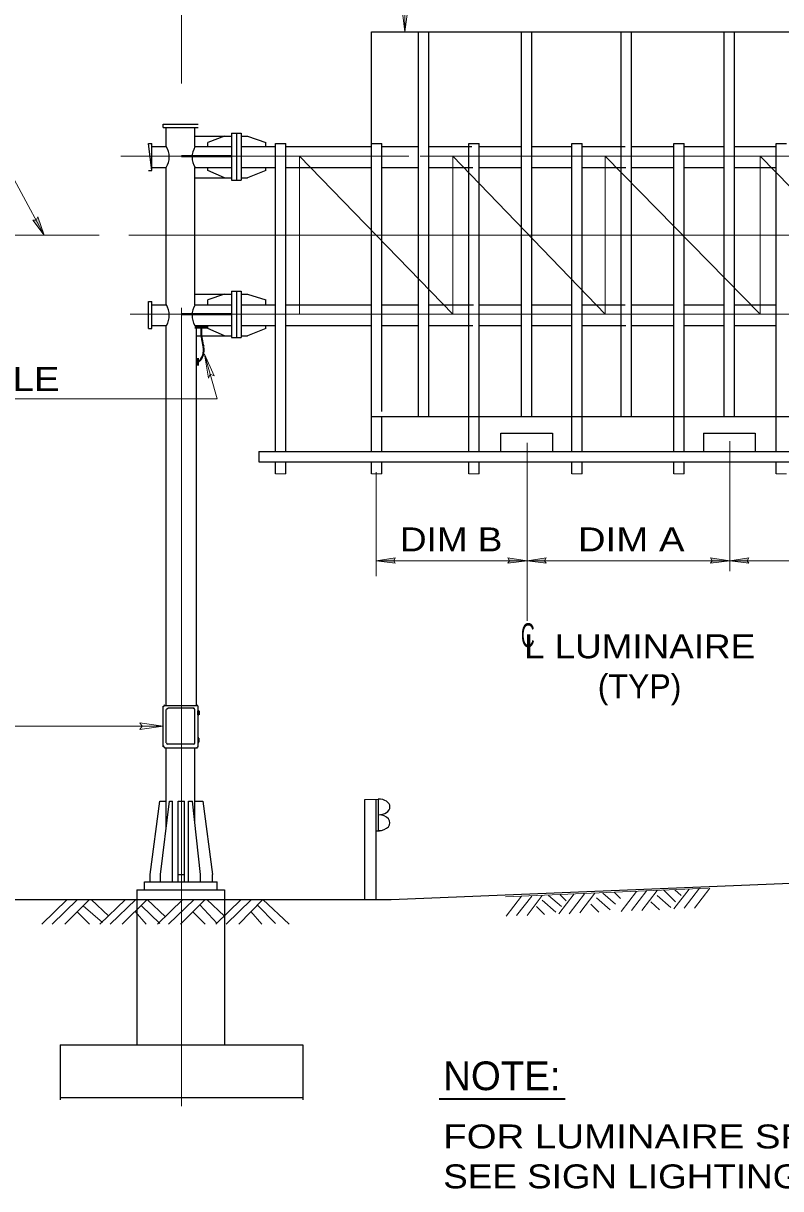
# Model space of a CAD drawing. Extents: x 312601.858 to 312602.699, y 144420.109 to 144420.704.
# Drawn here: x 312601.9635 to 312602.0584, y 144420.4634 to 144420.6093 of the extents above; entities that cross this region are included whole.
import ezdxf
from ezdxf.enums import TextEntityAlignment as Align

# ---------------------------------------------------------------- set-up
doc = ezdxf.new("R2010")
doc.units = 0
doc.header["$LTSCALE"] = 0.0012
for name, pattern in [('DOT_DASHED', [7.7, 5, -1.2, 0.3, -1.2]), ('LONG_DASH_SHORT_DASH', [9.9, 6, -1.2, 1.5, -1.2]), ('LONG_DASHED', [7.5, 6, -1.5])]:
    doc.linetypes.add(name, pattern=pattern)
for name, color, linetype, lineweight in [('1', 7, 'Continuous', 25), ('2', 7, 'Continuous', 25), ('39', 7, 'Continuous', 13)]:
    doc.layers.add(name, color=color, linetype=linetype, lineweight=lineweight)

msp = doc.modelspace()

# ---------------------------------------------------------------- hatches: boundary and pattern name
at = {"layer": '1'}
for points in [[(312601.9854, 144420.5232), (312601.9855, 144420.5232), (312601.9855, 144420.5227), (312601.9854, 144420.5227)], [(312601.9854, 144420.5193), (312601.9855, 144420.5193), (312601.9855, 144420.5198), (312601.9854, 144420.5198)]]:
    msp.add_hatch(color=256, dxfattribs=at).paths.add_polyline_path(points)
at = {"layer": '39'}
for points in [[(312601.9651, 144420.5847), (312601.9653, 144420.5851), (312601.9661, 144420.5828), (312601.9647, 144420.5847)], [(312602.0099, 144420.542), (312602.0101, 144420.5417), (312602.0077, 144420.542), (312602.0101, 144420.5424)], [(312602.0244, 144420.542), (312602.0242, 144420.5424), (312602.0266, 144420.542), (312602.0242, 144420.5417)], [(312602.0288, 144420.542), (312602.029, 144420.5417), (312602.0266, 144420.542), (312602.029, 144420.5424)], [(312602.0498, 144420.542), (312602.0496, 144420.5424), (312602.052, 144420.542), (312602.0496, 144420.5417)], [(312602.0542, 144420.542), (312602.0544, 144420.5417), (312602.052, 144420.542), (312602.0544, 144420.5424)]]:
    msp.add_hatch(color=256, dxfattribs=at).paths.add_polyline_path(points)

# ---------------------------------------------------------------- linework, layer by layer
at = {"layer": '1', "lineweight": 13}
for p, q in [((312601.9833, 144420.6415), (312601.9833, 144420.6018)), ((312602.0113, 144420.621), (312602.0113, 144420.6083)), ((312601.9548, 144420.5828), (312601.973, 144420.5828)), ((312601.9862, 144420.5679), (312601.9878, 144420.5623)), ((312601.9243, 144420.5623), (312601.9878, 144420.5623)), ((312601.9726, 144420.5623), (312601.9878, 144420.5623)), ((312601.9951, 144420.5529), (312601.9964, 144420.5529)), ((312602.0071, 144420.5529), (312602.0084, 144420.5529)), ((312602.0077, 144420.5401), (312602.0077, 144420.5531)), ((312602.0077, 144420.5437), (312602.0077, 144420.5531)), ((312602.0193, 144420.5529), (312602.0206, 144420.5529)), ((312602.0322, 144420.5529), (312602.0335, 144420.5529)), ((312602.045, 144420.5529), (312602.0463, 144420.5529)), ((312602.0578, 144420.5529), (312602.0591, 144420.5529)), ((312601.981, 144420.5213), (312601.9593, 144420.5213)), ((312601.981, 144420.5213), (312601.9605, 144420.5213)), ((312602.008, 144420.5121), (312602.0063, 144420.5121)), ((312601.9658, 144420.4965), (312601.969, 144420.4996)), ((312601.9671, 144420.4965), (312601.9703, 144420.4996)), ((312601.9687, 144420.4965), (312601.9718, 144420.4996)), ((312601.9734, 144420.4967), (312601.971, 144420.4988)), ((312601.9742, 144420.4975), (312601.972, 144420.4996)), ((312601.9731, 144420.4965), (312601.9763, 144420.4996)), ((312601.9744, 144420.4965), (312601.9776, 144420.4996)), ((312601.9759, 144420.4965), (312601.979, 144420.4996)), ((312601.9806, 144420.4966), (312601.9783, 144420.4988)), ((312601.9813, 144420.4974), (312601.979, 144420.4996)), ((312601.9803, 144420.4965), (312601.9835, 144420.4996)), ((312601.9817, 144420.4965), (312601.9849, 144420.4996)), ((312601.9832, 144420.4965), (312601.9863, 144420.4996)), ((312601.9878, 144420.4966), (312601.9856, 144420.4989)), ((312601.9887, 144420.4975), (312601.9865, 144420.4996)), ((312601.9876, 144420.4965), (312601.9908, 144420.4996)), ((312601.9889, 144420.4965), (312601.9921, 144420.4996)), ((312601.9905, 144420.4965), (312601.9935, 144420.4996)), ((312601.9951, 144420.4966), (312601.9928, 144420.4989)), ((312601.9968, 144420.4965), (312601.9935, 144420.4996)), ((312601.9718, 144420.4965), (312601.9702, 144420.4981)), ((312601.9789, 144420.4965), (312601.9775, 144420.4981)), ((312601.9863, 144420.4965), (312601.9847, 144420.4981)), ((312601.9934, 144420.4965), (312601.992, 144420.4981))]:
    msp.add_line(p, q, dxfattribs=at)
at = {"layer": '1', "linetype": 'LONG_DASH_SHORT_DASH', "lineweight": 13}
for p, q in [((312601.9833, 144420.4737), (312601.9833, 144420.6018)), ((312601.9757, 144420.5927), (312602.0118, 144420.5927)), ((312601.9769, 144420.5729), (312602.0559, 144420.5729))]:
    msp.add_line(p, q, dxfattribs=at)
at = {"layer": '1'}
for p, q in [((312601.981, 144420.5963), (312601.981, 144420.5967)), ((312601.981, 144420.5963), (312601.9854, 144420.5963)), ((312601.9814, 144420.5939), (312601.9814, 144420.5963)), ((312601.985, 144420.5939), (312601.985, 144420.5963)), ((312601.985, 144420.5952), (312601.9896, 144420.5952)), ((312601.9887, 144420.5952), (312601.9866, 144420.5944)), ((312601.9896, 144420.5956), (312601.9908, 144420.5956)), ((312601.9908, 144420.5952), (312601.9916, 144420.5952)), ((312601.9916, 144420.5952), (312601.9939, 144420.5944)), ((312601.9792, 144420.5943), (312601.9796, 144420.5943)), ((312601.9796, 144420.5909), (312601.9796, 144420.5943)), ((312601.9796, 144420.5939), (312601.9814, 144420.5939)), ((312601.985, 144420.5939), (312601.9896, 144420.5939)), ((312601.9866, 144420.5939), (312601.9866, 144420.5944)), ((312601.9908, 144420.5939), (312601.9951, 144420.5939)), ((312601.9939, 144420.5939), (312601.9939, 144420.5944)), ((312601.9964, 144420.5939), (312602.0071, 144420.5939)), ((312601.9796, 144420.5913), (312601.9814, 144420.5913)), ((312601.9814, 144420.5741), (312601.9814, 144420.5913)), ((312601.985, 144420.5741), (312601.985, 144420.5913)), ((312601.985, 144420.5913), (312601.9896, 144420.5913)), ((312601.9866, 144420.5909), (312601.9866, 144420.5913)), ((312601.9887, 144420.59), (312601.9866, 144420.5909)), ((312601.9908, 144420.5913), (312601.9951, 144420.5913)), ((312601.9939, 144420.5909), (312601.9916, 144420.59)), ((312601.9939, 144420.5909), (312601.9939, 144420.5913)), ((312601.9964, 144420.5913), (312602.0071, 144420.5913)), ((312601.985, 144420.59), (312601.9896, 144420.59)), ((312601.9896, 144420.5897), (312601.9908, 144420.5897)), ((312601.9908, 144420.59), (312601.9916, 144420.59)), ((312601.985, 144420.5754), (312601.9896, 144420.5754)), ((312601.9887, 144420.5754), (312601.9866, 144420.5747)), ((312601.9866, 144420.5741), (312601.9866, 144420.5747)), ((312601.9896, 144420.5758), (312601.9908, 144420.5758)), ((312601.9908, 144420.5754), (312601.9916, 144420.5754)), ((312601.9916, 144420.5754), (312601.9939, 144420.5747)), ((312601.9939, 144420.5741), (312601.9939, 144420.5747)), ((312601.9792, 144420.5745), (312601.9796, 144420.5745)), ((312601.9792, 144420.5711), (312601.9792, 144420.5745)), ((312601.9796, 144420.5711), (312601.9796, 144420.5745)), ((312601.9796, 144420.5741), (312601.9814, 144420.5741)), ((312601.985, 144420.5741), (312601.9896, 144420.5741)), ((312601.9908, 144420.5741), (312601.9951, 144420.5741)), ((312601.9964, 144420.5741), (312602.0071, 144420.5741)), ((312601.9792, 144420.5711), (312601.9796, 144420.5711)), ((312601.9796, 144420.5715), (312601.9814, 144420.5715)), ((312601.9814, 144420.5239), (312601.9814, 144420.5715)), ((312601.985, 144420.5715), (312601.9896, 144420.5715)), ((312601.9852, 144420.5239), (312601.9852, 144420.5715)), ((312601.9866, 144420.5711), (312601.9866, 144420.5715)), ((312601.9887, 144420.5702), (312601.9866, 144420.5711)), ((312601.9908, 144420.5715), (312601.9951, 144420.5715)), ((312601.9939, 144420.5711), (312601.9916, 144420.5702)), ((312601.9939, 144420.5711), (312601.9939, 144420.5715)), ((312601.9964, 144420.5715), (312602.0071, 144420.5715)), ((312601.9852, 144420.5702), (312601.9896, 144420.5702)), ((312601.9896, 144420.57), (312601.9908, 144420.57)), ((312601.9908, 144420.5702), (312601.9916, 144420.5702)), ((312602.0071, 144420.5601), (312602.0971, 144420.5601)), ((312601.993, 144420.5557), (312602.0971, 144420.5557)), ((312601.993, 144420.5544), (312602.0971, 144420.5544)), ((312601.981, 144420.5187), (312601.981, 144420.5238)), ((312601.9812, 144420.5239), (312601.9853, 144420.5239)), ((312601.9816, 144420.5236), (312601.9849, 144420.5236)), ((312601.9854, 144420.5187), (312601.9854, 144420.5238)), ((312601.9814, 144420.5192), (312601.9814, 144420.5234)), ((312601.985, 144420.5192), (312601.985, 144420.5234)), ((312601.9812, 144420.5186), (312601.9853, 144420.5186)), ((312601.9814, 144420.5086), (312601.9814, 144420.5186)), ((312601.9816, 144420.5191), (312601.9849, 144420.5191)), ((312601.985, 144420.5094), (312601.985, 144420.5186)), ((312601.9794, 144420.5027), (312601.9806, 144420.5119)), ((312601.9806, 144420.5119), (312601.9814, 144420.5119)), ((312601.9818, 144420.5119), (312601.9822, 144420.5119)), ((312601.9822, 144420.5018), (312601.9822, 144420.5119)), ((312601.9829, 144420.5119), (312601.9837, 144420.5119)), ((312601.9829, 144420.5018), (312601.9829, 144420.5119)), ((312601.9837, 144420.5018), (312601.9837, 144420.5119)), ((312601.985, 144420.5119), (312601.986, 144420.5119)), ((312601.986, 144420.5119), (312601.9872, 144420.5027)), ((312602.0077, 144420.5082), (312602.0081, 144420.5082)), ((312601.9787, 144420.5018), (312601.9878, 144420.5018)), ((312601.9787, 144420.5008), (312601.9787, 144420.5018)), ((312601.9794, 144420.5018), (312601.9794, 144420.5027)), ((312601.9807, 144420.5018), (312601.9807, 144420.5027)), ((312601.9829, 144420.5027), (312601.9837, 144420.5027)), ((312601.9857, 144420.5018), (312601.9857, 144420.5027)), ((312601.9872, 144420.5018), (312601.9872, 144420.5027)), ((312601.9878, 144420.5008), (312601.9878, 144420.5018)), ((312602.0096, 144420.4996), (312602.0958, 144420.5031)), ((312601.9777, 144420.5008), (312601.9887, 144420.5008)), ((312601.9566, 144420.4996), (312602.0096, 144420.4996))]:
    msp.add_line(p, q, dxfattribs=at)
at = {"layer": '1', "lineweight": 40}
for p, q in [((312601.9833, 144420.5927), (312601.9896, 144420.5927)), ((312601.9833, 144420.5729), (312601.9896, 144420.5729))]:
    msp.add_line(p, q, dxfattribs=at)
at = {"layer": '1', "linetype": 'DOT_DASHED', "lineweight": 13}
msp.add_line((312601.9767, 144420.5828), (312602.1035, 144420.5828), dxfattribs=at)
at = {"layer": '1', "lineweight": 35}
for p, q in [((312601.9866, 144420.5713), (312601.985, 144420.5713)), ((312601.9866, 144420.5712), (312601.985, 144420.5712)), ((312601.9858, 144420.5712), (312601.9858, 144420.5708)), ((312601.9853, 144420.5665), (312601.9853, 144420.5674)), ((312601.9854, 144420.5665), (312601.9854, 144420.5674)), ((312602.0156, 144420.4746), (312602.0314, 144420.4746))]:
    msp.add_line(p, q, dxfattribs=at)
at = {"layer": '1', "linetype": 'LONG_DASHED'}
for p, q in [((312601.9777, 144420.5008), (312601.9777, 144420.4814)), ((312601.9887, 144420.5008), (312601.9887, 144420.4814)), ((312601.9681, 144420.4814), (312601.9985, 144420.4814)), ((312601.9681, 144420.4814), (312601.9681, 144420.4745)), ((312601.9985, 144420.4814), (312601.9985, 144420.4745)), ((312601.9681, 144420.4748), (312601.9985, 144420.4748))]:
    msp.add_line(p, q, dxfattribs=at)
at = {"layer": '1', "lineweight": 13}
for points in [[(312602.0117, 144420.6114), (312602.0113, 144420.6083), (312602.0109, 144420.6114), (312602.0113, 144420.6109)], [(312601.9867, 144420.5649), (312601.9862, 144420.5679), (312601.9874, 144420.5652), (312601.9869, 144420.5654)], [(312601.9781, 144420.5217), (312601.981, 144420.5213), (312601.9781, 144420.5209), (312601.9784, 144420.5213)]]:
    msp.add_lwpolyline(points, close=True, dxfattribs=at)
at = {"layer": '1'}
for points in [[(312601.981, 144420.5967), (312601.9854, 144420.5967), (312601.9854, 144420.5967)], [(312601.9792, 144420.5909), (312601.9796, 144420.5909), (312601.9792, 144420.5943)], [(312601.9842, 144420.5018), (312601.9842, 144420.5119), (312601.9847, 144420.5119)]]:
    msp.add_lwpolyline(points, dxfattribs=at)
at = {"layer": '1', "lineweight": 13}
msp.add_lwpolyline([(312602.0077, 144420.542), (312602.0266, 144420.542), (312602.052, 144420.542), (312602.0778, 144420.542), (312602.0965, 144420.542)], dxfattribs=at)
at = {"layer": '1', "linetype": 'LONG_DASHED', "lineweight": 35}
for points in [[(312601.9854, 144420.5232), (312601.9855, 144420.5232), (312601.9855, 144420.5227), (312601.9854, 144420.5227)], [(312601.9854, 144420.5193), (312601.9855, 144420.5193), (312601.9855, 144420.5198), (312601.9854, 144420.5198)]]:
    msp.add_lwpolyline(points, close=True, dxfattribs=at)
at = {"layer": '1', "lineweight": 35}
for centre, radius, start, end in [((312601.991931, 144420.570634), 0.006142, 178.65609, 196.96615), ((312601.984216, 144420.568372), 0.001899, 309.51694, 14.29816)]:
    msp.add_arc(centre, radius, start, end, dxfattribs=at)
at = {"layer": '1'}
for centre, start, end in [((312601.981227, 144420.523739), 90, 180), ((312601.985217, 144420.523739), 0, 90), ((312601.981623, 144420.523343), 90, 180), ((312601.984821, 144420.523343), 0, 90), ((312601.981623, 144420.519221), 180, 270), ((312601.984821, 144420.519221), 270, 0), ((312601.981211, 144420.518823), 180, 270), ((312601.985241, 144420.518823), 270, 0)]:
    msp.add_arc(centre, 0.000183, start, end, dxfattribs=at)
for centre, major_axis, ratio, start_param, end_param in [((312601.979334, 144420.592643), (0.001314, -0.002112), 0.975936, 0.450065, 1.5707963), ((312601.987019, 144420.592643), (0.001282, 0.002061), 0.971215, 1.5832282, 2.7139963), ((312601.979334, 144420.57286), (0.001326, -0.002132), 0.966698, 0.4506841, 1.5509312), ((312601.987019, 144420.57286), (0.001302, 0.002093), 0.95266, 1.571263, 2.6992129), ((312602.007972, 144420.511184), (0.001455, 0), 0.680301, 4.712389, 7.8539816), ((312602.007972, 144420.509204), (-0.001455, 0), 0.680301, 1.5707963, 4.712389)]:
    msp.add_ellipse(centre, major_axis=major_axis, ratio=ratio, start_param=start_param, end_param=end_param, dxfattribs=at)
at = {"layer": '2'}
for p, q in [((312602.0071, 144420.6083), (312602.0971, 144420.6083)), ((312602.0071, 144420.5557), (312602.0071, 144420.6083)), ((312601.9896, 144420.5956), (312601.9896, 144420.5897)), ((312601.9902, 144420.5956), (312601.9902, 144420.5897)), ((312601.9908, 144420.5956), (312601.9908, 144420.5897)), ((312601.9951, 144420.5943), (312601.9964, 144420.5943)), ((312601.9951, 144420.5557), (312601.9951, 144420.5943)), ((312601.9964, 144420.5557), (312601.9964, 144420.5943)), ((312602.0071, 144420.5943), (312602.0084, 144420.5943)), ((312602.0193, 144420.5943), (312602.0206, 144420.5943)), ((312602.0322, 144420.5943), (312602.0335, 144420.5943)), ((312602.045, 144420.5943), (312602.0463, 144420.5943)), ((312602.0578, 144420.5943), (312602.0591, 144420.5943)), ((312601.9896, 144420.5758), (312601.9896, 144420.57)), ((312601.9902, 144420.5758), (312601.9902, 144420.57)), ((312601.9908, 144420.5758), (312601.9908, 144420.57)), ((312602.0084, 144420.5557), (312602.0084, 144420.5601)), ((312602.0193, 144420.5557), (312602.0193, 144420.5601)), ((312602.0206, 144420.5557), (312602.0206, 144420.5601)), ((312602.0322, 144420.5557), (312602.0322, 144420.5601)), ((312602.0335, 144420.5557), (312602.0335, 144420.5601)), ((312602.045, 144420.5557), (312602.045, 144420.5601)), ((312602.0463, 144420.5557), (312602.0463, 144420.5601)), ((312602.0578, 144420.5557), (312602.0578, 144420.5601)), ((312602.0487, 144420.558), (312602.0552, 144420.558)), ((312602.0487, 144420.558), (312602.0487, 144420.5557)), ((312602.0552, 144420.558), (312602.0552, 144420.5557)), ((312601.993, 144420.5557), (312601.993, 144420.5544)), ((312601.9951, 144420.5529), (312601.9951, 144420.5544)), ((312601.9964, 144420.5529), (312601.9964, 144420.5544)), ((312602.0071, 144420.5529), (312602.0071, 144420.5544)), ((312602.0084, 144420.5529), (312602.0084, 144420.5544)), ((312602.0193, 144420.5529), (312602.0193, 144420.5544)), ((312602.0206, 144420.5529), (312602.0206, 144420.5544)), ((312602.0322, 144420.5529), (312602.0322, 144420.5544)), ((312602.0335, 144420.5529), (312602.0335, 144420.5544)), ((312602.045, 144420.5529), (312602.045, 144420.5544)), ((312602.0463, 144420.5529), (312602.0463, 144420.5544)), ((312602.0578, 144420.5529), (312602.0578, 144420.5544)), ((312601.9807, 144420.5027), (312601.9818, 144420.5119)), ((312601.9857, 144420.5027), (312601.9847, 144420.5119)), ((312602.0063, 144420.4996), (312602.0063, 144420.5121)), ((312602.0077, 144420.4996), (312602.0077, 144420.5121)), ((312602.008, 144420.5082), (312602.008, 144420.5121))]:
    msp.add_line(p, q, dxfattribs=at)
at = {"layer": '2', "linetype": 'LONG_DASHED'}
for p, q in [((312602.013, 144420.5601), (312602.013, 144420.6083)), ((312602.0143, 144420.5601), (312602.0143, 144420.6083)), ((312602.0259, 144420.5601), (312602.0259, 144420.6083)), ((312602.0272, 144420.5601), (312602.0272, 144420.6083)), ((312602.0384, 144420.5601), (312602.0384, 144420.6083)), ((312602.0397, 144420.5601), (312602.0397, 144420.6083)), ((312602.0513, 144420.5601), (312602.0513, 144420.6083)), ((312602.0526, 144420.5601), (312602.0526, 144420.6083)), ((312602.0084, 144420.5607), (312602.0084, 144420.5943)), ((312602.0084, 144420.5939), (312602.013, 144420.5939)), ((312602.0143, 144420.5939), (312602.0197, 144420.5939)), ((312602.0193, 144420.5601), (312602.0193, 144420.5943)), ((312602.0206, 144420.5601), (312602.0206, 144420.5943)), ((312602.0206, 144420.5939), (312602.0259, 144420.5939)), ((312602.0272, 144420.5939), (312602.0322, 144420.5939)), ((312602.0322, 144420.5601), (312602.0322, 144420.5943)), ((312602.0335, 144420.5601), (312602.0335, 144420.5943)), ((312602.0335, 144420.5939), (312602.0389, 144420.5939)), ((312602.0397, 144420.5939), (312602.045, 144420.5939)), ((312602.045, 144420.5601), (312602.045, 144420.5943)), ((312602.0463, 144420.5601), (312602.0463, 144420.5943)), ((312602.0463, 144420.5939), (312602.0513, 144420.5939)), ((312602.0526, 144420.5939), (312602.0578, 144420.5939)), ((312602.0578, 144420.5601), (312602.0578, 144420.5943)), ((312602.0084, 144420.5913), (312602.013, 144420.5913)), ((312602.0143, 144420.5913), (312602.0198, 144420.5913)), ((312602.0206, 144420.5913), (312602.0259, 144420.5913)), ((312602.0272, 144420.5913), (312602.0322, 144420.5913)), ((312602.0335, 144420.5913), (312602.039, 144420.5913)), ((312602.0397, 144420.5913), (312602.045, 144420.5913)), ((312602.0463, 144420.5913), (312602.0513, 144420.5913)), ((312602.0526, 144420.5913), (312602.0578, 144420.5913)), ((312602.0084, 144420.5741), (312602.013, 144420.5741)), ((312602.0143, 144420.5741), (312602.0199, 144420.5741)), ((312602.0206, 144420.5741), (312602.0259, 144420.5741)), ((312602.0272, 144420.5741), (312602.0322, 144420.5741)), ((312602.0335, 144420.5741), (312602.0389, 144420.5741)), ((312602.0397, 144420.5741), (312602.045, 144420.5741)), ((312602.0463, 144420.5741), (312602.0513, 144420.5741)), ((312602.0526, 144420.5741), (312602.0578, 144420.5741)), ((312602.0084, 144420.5715), (312602.013, 144420.5715)), ((312602.0143, 144420.5715), (312602.0198, 144420.5715)), ((312602.0206, 144420.5715), (312602.0259, 144420.5715)), ((312602.0272, 144420.5715), (312602.0322, 144420.5715)), ((312602.0335, 144420.5715), (312602.039, 144420.5715)), ((312602.0397, 144420.5715), (312602.045, 144420.5715)), ((312602.0463, 144420.5715), (312602.0513, 144420.5715)), ((312602.0526, 144420.5715), (312602.0578, 144420.5715))]:
    msp.add_line(p, q, dxfattribs=at)
at = {"layer": '2', "lineweight": 13}
for p, q in [((312601.9586, 144420.5967), (312601.9661, 144420.5828)), ((312602.0266, 144420.5568), (312602.0266, 144420.5345)), ((312602.052, 144420.557), (312602.052, 144420.5407)), ((312602.0239, 144420.4999), (312602.0493, 144420.501)), ((312602.0306, 144420.4978), (312602.0325, 144420.5003)), ((312602.0307, 144420.5002), (312602.0315, 144420.4994)), ((312602.0319, 144420.4978), (312602.0338, 144420.5003)), ((312602.0332, 144420.4979), (312602.0351, 144420.5004)), ((312602.0361, 144420.5004), (312602.0377, 144420.499)), ((312602.0375, 144420.5005), (312602.0383, 144420.4997)), ((312602.0384, 144420.4981), (312602.0403, 144420.5006)), ((312602.0397, 144420.4982), (312602.0416, 144420.5007)), ((312602.041, 144420.4982), (312602.0429, 144420.5007)), ((312602.0437, 144420.5008), (312602.0452, 144420.4993)), ((312602.045, 144420.4984), (312602.0469, 144420.5009)), ((312602.0451, 144420.5008), (312602.0459, 144420.5001)), ((312602.0463, 144420.4985), (312602.0482, 144420.501)), ((312602.0476, 144420.4985), (312602.0495, 144420.501)), ((312602.024, 144420.4975), (312602.0259, 144420.5)), ((312602.0253, 144420.4976), (312602.0272, 144420.5)), ((312602.0266, 144420.4976), (312602.0285, 144420.5001)), ((312602.0285, 144420.4995), (312602.0302, 144420.498)), ((312602.0293, 144420.5001), (312602.0309, 144420.4987)), ((312602.0346, 144420.499), (312602.0356, 144420.498)), ((312602.0353, 144420.4998), (312602.037, 144420.4983)), ((312602.0421, 144420.4993), (312602.0432, 144420.4983)), ((312602.0429, 144420.5001), (312602.0446, 144420.4986)), ((312602.0278, 144420.4987), (312602.0288, 144420.4977))]:
    msp.add_line(p, q, dxfattribs=at)
at = {"layer": '2', "linetype": 'LONG_DASH_SHORT_DASH', "lineweight": 13}
for p, q in [((312602.0397, 144420.5962), (312602.0397, 144420.5764)), ((312601.9981, 144420.5927), (312602.0173, 144420.5729)), ((312601.9981, 144420.5927), (312601.9981, 144420.5729)), ((312602.0132, 144420.5927), (312602.1021, 144420.5927)), ((312602.0173, 144420.5927), (312602.0364, 144420.5729)), ((312602.0173, 144420.5927), (312602.0173, 144420.5729)), ((312602.0364, 144420.5927), (312602.0364, 144420.5729)), ((312602.0558, 144420.5927), (312602.0558, 144420.5729))]:
    msp.add_line(p, q, dxfattribs=at)
for points in [[(312602.0364, 144420.5927), (312602.0558, 144420.5729), (312602.0751, 144420.5729)], [(312602.0558, 144420.5927), (312602.0751, 144420.5729), (312602.1016, 144420.5729)]]:
    msp.add_lwpolyline(points, dxfattribs=at)
at = {"layer": '2'}
msp.add_lwpolyline([(312602.0233, 144420.5557), (312602.0233, 144420.558), (312602.0298, 144420.558), (312602.0298, 144420.5557)], dxfattribs=at)
at = {"layer": '39'}
for points in [[(312601.9651, 144420.5847), (312601.9653, 144420.5851), (312601.9661, 144420.5828), (312601.9647, 144420.5847)], [(312602.0099, 144420.542), (312602.0101, 144420.5417), (312602.0077, 144420.542), (312602.0101, 144420.5424)], [(312602.0244, 144420.542), (312602.0242, 144420.5424), (312602.0266, 144420.542), (312602.0242, 144420.5417)], [(312602.0288, 144420.542), (312602.029, 144420.5417), (312602.0266, 144420.542), (312602.029, 144420.5424)], [(312602.0498, 144420.542), (312602.0496, 144420.5424), (312602.052, 144420.542), (312602.0496, 144420.5417)], [(312602.0542, 144420.542), (312602.0544, 144420.5417), (312602.052, 144420.542), (312602.0544, 144420.5424)]]:
    msp.add_lwpolyline(points, close=True, dxfattribs=at)

# ---------------------------------------------------------------- texts
at = {"layer": '1'}
for s, width, p in [('41 MM o FLEXIBLE', 1.2, (312601.9255, 144420.5633)), ('FOR LUMINAIRE SPACING DIMENSIONS "A" & "B"', 1.2, (312602.0161, 144420.4684)), ('SEE SIGN LIGHTING ASSEMBLY DETAIL.', 1.15, (312602.0161, 144420.4634))]:
    msp.add_text(s, height=0.003, dxfattribs=dict(at, width=width)).set_placement(p)
for s, width, p in [('DIM B', 1.15, (312602.0171, 144420.5432)), ('DIM A', 1.2, (312602.03965, 144420.5432))]:
    msp.add_text(s, height=0.003, dxfattribs=dict(at, width=width)).set_placement(p, align=Align.CENTER)
msp.add_text('NOTE:', height=0.0036, dxfattribs=at).set_placement((312602.02345, 144420.4757), align=Align.CENTER)
at = {"layer": '2'}
for s, width, p in [('C', 0.6, (312602.0267, 144420.5312)), ('L LUMINAIRE', 1.15, (312602.0407, 144420.5298))]:
    msp.add_text(s, height=0.003, dxfattribs=dict(at, width=width)).set_placement(p, align=Align.CENTER)
msp.add_text('(TYP)', height=0.003, dxfattribs=at).set_placement((312602.0407, 144420.5248), align=Align.CENTER)

doc.saveas('drawing.dxf')
